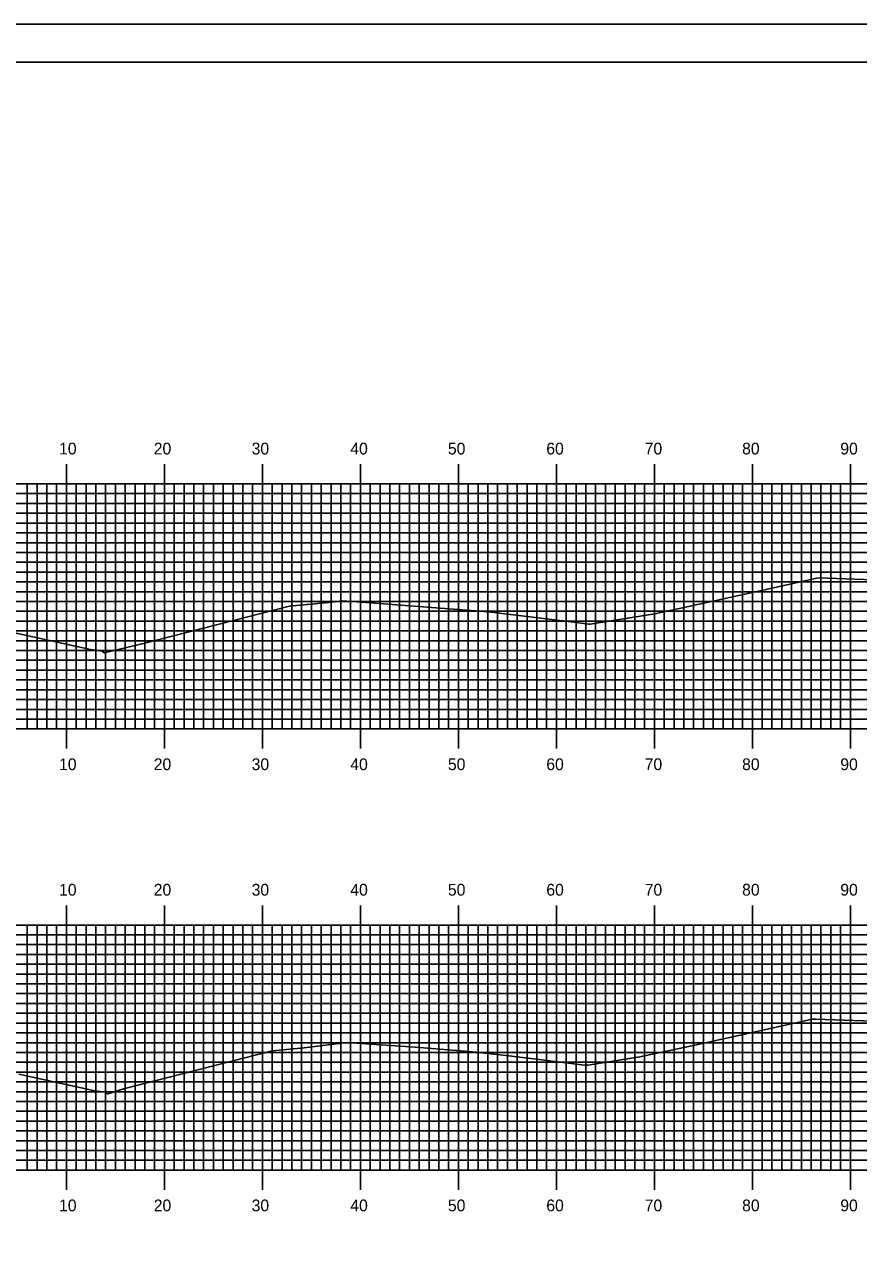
# Model space of a CAD drawing. Extents: x 855468 to 855811, y 366605 to 366825.
# Drawn here: x 855639.3 to 855724.4, y 366701.1 to 366824.9 of the extents above; entities that cross this region are included whole.
import ezdxf

# ---------------------------------------------------------------- set-up
doc = ezdxf.new("R2010")
doc.units = 0
for name, color, linetype in [('BORDER', 7, 'Continuous'), ('H_V ANNOTATION', 7, 'Continuous'), ('MAJOR', 7, 'Continuous'), ('MINOR', 7, 'Continuous'), ('PLOT BOUNDARY', 7, 'Continuous'), ('S_Roadway_Centerline', 7, 'Continuous')]:
    doc.layers.add(name, color=color, linetype=linetype)

msp = doc.modelspace()

# ---------------------------------------------------------------- linework, layer by layer
at = {"layer": 'BORDER'}
msp.add_lwpolyline([(855483.98, 366611.06), (855803.98, 366611.06), (855803.98, 366821.06), (855483.98, 366821.06)], close=True, dxfattribs=at)
at = {"layer": 'MAJOR'}
for p, q in [((855643.58, 366780.06), (855643.58, 366778.06)), ((855653.58, 366780.06), (855653.58, 366778.06)), ((855663.58, 366780.06), (855663.58, 366778.06)), ((855673.58, 366780.06), (855673.58, 366778.06)), ((855683.58, 366780.06), (855683.58, 366778.06)), ((855693.58, 366780.06), (855693.58, 366778.06)), ((855703.58, 366780.06), (855703.58, 366778.06)), ((855713.58, 366780.06), (855713.58, 366778.06)), ((855723.58, 366780.06), (855723.58, 366778.06)), ((855493.58, 366778.06), (855773.58, 366778.06)), ((855493.58, 366778.06), (855773.58, 366778.06)), ((855643.58, 366753.06), (855643.58, 366778.06)), ((855653.58, 366753.06), (855653.58, 366778.06)), ((855663.58, 366753.06), (855663.58, 366778.06)), ((855673.58, 366753.06), (855673.58, 366778.06)), ((855683.58, 366753.06), (855683.58, 366778.06)), ((855693.58, 366753.06), (855693.58, 366778.06)), ((855703.58, 366753.06), (855703.58, 366778.06)), ((855713.58, 366753.06), (855713.58, 366778.06)), ((855723.58, 366753.06), (855723.58, 366778.06)), ((855493.58, 366773.06), (855773.58, 366773.06)), ((855493.58, 366768.06), (855773.58, 366768.06)), ((855493.58, 366763.06), (855773.58, 366763.06)), ((855493.58, 366758.06), (855773.58, 366758.06)), ((855493.58, 366753.06), (855773.58, 366753.06)), ((855493.58, 366753.06), (855773.58, 366753.06)), ((855643.58, 366751.05), (855643.58, 366753.06)), ((855653.58, 366751.05), (855653.58, 366753.06)), ((855663.58, 366751.05), (855663.58, 366753.06)), ((855673.58, 366751.05), (855673.58, 366753.06)), ((855683.58, 366751.05), (855683.58, 366753.06)), ((855693.58, 366751.05), (855693.58, 366753.06)), ((855703.58, 366751.05), (855703.58, 366753.06)), ((855713.58, 366751.05), (855713.58, 366753.06)), ((855723.58, 366751.05), (855723.58, 366753.06)), ((855643.58, 366735.06), (855643.58, 366733.06)), ((855653.58, 366735.06), (855653.58, 366733.06)), ((855663.58, 366735.06), (855663.58, 366733.06)), ((855673.58, 366735.06), (855673.58, 366733.06)), ((855683.58, 366735.06), (855683.58, 366733.06)), ((855693.58, 366735.06), (855693.58, 366733.06)), ((855703.58, 366735.06), (855703.58, 366733.06)), ((855713.58, 366735.06), (855713.58, 366733.06)), ((855723.58, 366735.06), (855723.58, 366733.06)), ((855493.58, 366733.06), (855773.58, 366733.06)), ((855493.58, 366733.06), (855773.58, 366733.06)), ((855643.58, 366708.06), (855643.58, 366733.06)), ((855653.58, 366708.06), (855653.58, 366733.06)), ((855663.58, 366708.06), (855663.58, 366733.06)), ((855673.58, 366708.06), (855673.58, 366733.06)), ((855683.58, 366708.06), (855683.58, 366733.06)), ((855693.58, 366708.06), (855693.58, 366733.06)), ((855703.58, 366708.06), (855703.58, 366733.06)), ((855713.58, 366708.06), (855713.58, 366733.06)), ((855723.58, 366708.06), (855723.58, 366733.06)), ((855493.58, 366728.06), (855773.58, 366728.06)), ((855493.58, 366723.06), (855773.58, 366723.06)), ((855493.58, 366718.06), (855773.58, 366718.06)), ((855493.58, 366713.06), (855773.58, 366713.06)), ((855493.58, 366708.06), (855773.58, 366708.06)), ((855493.58, 366708.06), (855773.58, 366708.06)), ((855643.58, 366706.05), (855643.58, 366708.06)), ((855653.58, 366706.05), (855653.58, 366708.06)), ((855663.58, 366706.05), (855663.58, 366708.06)), ((855673.58, 366706.05), (855673.58, 366708.06)), ((855683.58, 366706.05), (855683.58, 366708.06)), ((855693.58, 366706.05), (855693.58, 366708.06)), ((855703.58, 366706.05), (855703.58, 366708.06)), ((855713.58, 366706.05), (855713.58, 366708.06)), ((855723.58, 366706.05), (855723.58, 366708.06))]:
    msp.add_line(p, q, dxfattribs=at)
at = {"layer": 'MINOR'}
for p, q in [((855639.58, 366753.06), (855639.58, 366778.06)), ((855640.58, 366753.06), (855640.58, 366778.06)), ((855641.58, 366753.06), (855641.58, 366778.06)), ((855642.58, 366753.06), (855642.58, 366778.06)), ((855644.58, 366753.06), (855644.58, 366778.06)), ((855645.58, 366753.06), (855645.58, 366778.06)), ((855646.58, 366753.06), (855646.58, 366778.06)), ((855647.58, 366753.06), (855647.58, 366778.06)), ((855648.58, 366753.06), (855648.58, 366778.06)), ((855649.58, 366753.06), (855649.58, 366778.06)), ((855650.58, 366753.06), (855650.58, 366778.06)), ((855651.58, 366753.06), (855651.58, 366778.06)), ((855652.58, 366753.06), (855652.58, 366778.06)), ((855654.58, 366753.06), (855654.58, 366778.06)), ((855655.58, 366753.06), (855655.58, 366778.06)), ((855656.58, 366753.06), (855656.58, 366778.06)), ((855657.58, 366753.06), (855657.58, 366778.06)), ((855658.58, 366753.06), (855658.58, 366778.06)), ((855659.58, 366753.06), (855659.58, 366778.06)), ((855660.58, 366753.06), (855660.58, 366778.06)), ((855661.58, 366753.06), (855661.58, 366778.06)), ((855662.58, 366753.06), (855662.58, 366778.06)), ((855664.58, 366753.06), (855664.58, 366778.06)), ((855665.58, 366753.06), (855665.58, 366778.06)), ((855666.58, 366753.06), (855666.58, 366778.06)), ((855667.58, 366753.06), (855667.58, 366778.06)), ((855668.58, 366753.06), (855668.58, 366778.06)), ((855669.58, 366753.06), (855669.58, 366778.06)), ((855670.58, 366753.06), (855670.58, 366778.06)), ((855671.58, 366753.06), (855671.58, 366778.06)), ((855672.58, 366753.06), (855672.58, 366778.06)), ((855674.58, 366753.06), (855674.58, 366778.06)), ((855675.58, 366753.06), (855675.58, 366778.06)), ((855676.58, 366753.06), (855676.58, 366778.06)), ((855677.58, 366753.06), (855677.58, 366778.06)), ((855678.58, 366753.06), (855678.58, 366778.06)), ((855679.58, 366753.06), (855679.58, 366778.06)), ((855680.58, 366753.06), (855680.58, 366778.06)), ((855681.58, 366753.06), (855681.58, 366778.06)), ((855682.58, 366753.06), (855682.58, 366778.06)), ((855684.58, 366753.06), (855684.58, 366778.06)), ((855685.58, 366753.06), (855685.58, 366778.06)), ((855686.58, 366753.06), (855686.58, 366778.06)), ((855687.58, 366753.06), (855687.58, 366778.06)), ((855688.58, 366753.06), (855688.58, 366778.06)), ((855689.58, 366753.06), (855689.58, 366778.06)), ((855690.58, 366753.06), (855690.58, 366778.06)), ((855691.58, 366753.06), (855691.58, 366778.06)), ((855692.58, 366753.06), (855692.58, 366778.06)), ((855694.58, 366753.06), (855694.58, 366778.06)), ((855695.58, 366753.06), (855695.58, 366778.06)), ((855696.58, 366753.06), (855696.58, 366778.06)), ((855697.58, 366753.06), (855697.58, 366778.06)), ((855698.58, 366753.06), (855698.58, 366778.06)), ((855699.58, 366753.06), (855699.58, 366778.06)), ((855700.58, 366753.06), (855700.58, 366778.06)), ((855701.58, 366753.06), (855701.58, 366778.06)), ((855702.58, 366753.06), (855702.58, 366778.06)), ((855704.58, 366753.06), (855704.58, 366778.06)), ((855705.58, 366753.06), (855705.58, 366778.06)), ((855706.58, 366753.06), (855706.58, 366778.06)), ((855707.58, 366753.06), (855707.58, 366778.06)), ((855708.58, 366753.06), (855708.58, 366778.06)), ((855709.58, 366753.06), (855709.58, 366778.06)), ((855710.58, 366753.06), (855710.58, 366778.06)), ((855711.58, 366753.06), (855711.58, 366778.06)), ((855712.58, 366753.06), (855712.58, 366778.06)), ((855714.58, 366753.06), (855714.58, 366778.06)), ((855715.58, 366753.06), (855715.58, 366778.06)), ((855716.58, 366753.06), (855716.58, 366778.06)), ((855717.58, 366753.06), (855717.58, 366778.06)), ((855718.58, 366753.06), (855718.58, 366778.06)), ((855719.58, 366753.06), (855719.58, 366778.06)), ((855720.58, 366753.06), (855720.58, 366778.06)), ((855721.58, 366753.06), (855721.58, 366778.06)), ((855722.58, 366753.06), (855722.58, 366778.06)), ((855493.58, 366777.06), (855773.58, 366777.06)), ((855493.58, 366776.06), (855773.58, 366776.06)), ((855493.58, 366775.06), (855773.58, 366775.06)), ((855493.58, 366774.06), (855773.58, 366774.06)), ((855493.58, 366772.06), (855773.58, 366772.06)), ((855493.58, 366771.06), (855773.58, 366771.06)), ((855493.58, 366770.06), (855773.58, 366770.06)), ((855493.58, 366769.06), (855773.58, 366769.06)), ((855493.58, 366767.06), (855773.58, 366767.06)), ((855493.58, 366766.06), (855773.58, 366766.06)), ((855493.58, 366765.06), (855773.58, 366765.06)), ((855493.58, 366764.06), (855773.58, 366764.06)), ((855493.58, 366762.06), (855773.58, 366762.06)), ((855493.58, 366761.06), (855773.58, 366761.06)), ((855493.58, 366760.06), (855773.58, 366760.06)), ((855493.58, 366759.06), (855773.58, 366759.06)), ((855493.58, 366757.06), (855773.58, 366757.06)), ((855493.58, 366756.06), (855773.58, 366756.06)), ((855493.58, 366755.06), (855773.58, 366755.06)), ((855493.58, 366754.06), (855773.58, 366754.06)), ((855639.58, 366708.06), (855639.58, 366733.06)), ((855640.58, 366708.06), (855640.58, 366733.06)), ((855641.58, 366708.06), (855641.58, 366733.06)), ((855642.58, 366708.06), (855642.58, 366733.06)), ((855644.58, 366708.06), (855644.58, 366733.06)), ((855645.58, 366708.06), (855645.58, 366733.06)), ((855646.58, 366708.06), (855646.58, 366733.06)), ((855647.58, 366708.06), (855647.58, 366733.06)), ((855648.58, 366708.06), (855648.58, 366733.06)), ((855649.58, 366708.06), (855649.58, 366733.06)), ((855650.58, 366708.06), (855650.58, 366733.06)), ((855651.58, 366708.06), (855651.58, 366733.06)), ((855652.58, 366708.06), (855652.58, 366733.06)), ((855654.58, 366708.06), (855654.58, 366733.06)), ((855655.58, 366708.06), (855655.58, 366733.06)), ((855656.58, 366708.06), (855656.58, 366733.06)), ((855657.58, 366708.06), (855657.58, 366733.06)), ((855658.58, 366708.06), (855658.58, 366733.06)), ((855659.58, 366708.06), (855659.58, 366733.06)), ((855660.58, 366708.06), (855660.58, 366733.06)), ((855661.58, 366708.06), (855661.58, 366733.06)), ((855662.58, 366708.06), (855662.58, 366733.06)), ((855664.58, 366708.06), (855664.58, 366733.06)), ((855665.58, 366708.06), (855665.58, 366733.06)), ((855666.58, 366708.06), (855666.58, 366733.06)), ((855667.58, 366708.06), (855667.58, 366733.06)), ((855668.58, 366708.06), (855668.58, 366733.06)), ((855669.58, 366708.06), (855669.58, 366733.06)), ((855670.58, 366708.06), (855670.58, 366733.06)), ((855671.58, 366708.06), (855671.58, 366733.06)), ((855672.58, 366708.06), (855672.58, 366733.06)), ((855674.58, 366708.06), (855674.58, 366733.06)), ((855675.58, 366708.06), (855675.58, 366733.06)), ((855676.58, 366708.06), (855676.58, 366733.06)), ((855677.58, 366708.06), (855677.58, 366733.06)), ((855678.58, 366708.06), (855678.58, 366733.06)), ((855679.58, 366708.06), (855679.58, 366733.06)), ((855680.58, 366708.06), (855680.58, 366733.06)), ((855681.58, 366708.06), (855681.58, 366733.06)), ((855682.58, 366708.06), (855682.58, 366733.06)), ((855684.58, 366708.06), (855684.58, 366733.06)), ((855685.58, 366708.06), (855685.58, 366733.06)), ((855686.58, 366708.06), (855686.58, 366733.06)), ((855687.58, 366708.06), (855687.58, 366733.06)), ((855688.58, 366708.06), (855688.58, 366733.06)), ((855689.58, 366708.06), (855689.58, 366733.06)), ((855690.58, 366708.06), (855690.58, 366733.06)), ((855691.58, 366708.06), (855691.58, 366733.06)), ((855692.58, 366708.06), (855692.58, 366733.06)), ((855694.58, 366708.06), (855694.58, 366733.06)), ((855695.58, 366708.06), (855695.58, 366733.06)), ((855696.58, 366708.06), (855696.58, 366733.06)), ((855697.58, 366708.06), (855697.58, 366733.06)), ((855698.58, 366708.06), (855698.58, 366733.06)), ((855699.58, 366708.06), (855699.58, 366733.06)), ((855700.58, 366708.06), (855700.58, 366733.06)), ((855701.58, 366708.06), (855701.58, 366733.06)), ((855702.58, 366708.06), (855702.58, 366733.06)), ((855704.58, 366708.06), (855704.58, 366733.06)), ((855705.58, 366708.06), (855705.58, 366733.06)), ((855706.58, 366708.06), (855706.58, 366733.06)), ((855707.58, 366708.06), (855707.58, 366733.06)), ((855708.58, 366708.06), (855708.58, 366733.06)), ((855709.58, 366708.06), (855709.58, 366733.06)), ((855710.58, 366708.06), (855710.58, 366733.06)), ((855711.58, 366708.06), (855711.58, 366733.06)), ((855712.58, 366708.06), (855712.58, 366733.06)), ((855714.58, 366708.06), (855714.58, 366733.06)), ((855715.58, 366708.06), (855715.58, 366733.06)), ((855716.58, 366708.06), (855716.58, 366733.06)), ((855717.58, 366708.06), (855717.58, 366733.06)), ((855718.58, 366708.06), (855718.58, 366733.06)), ((855719.58, 366708.06), (855719.58, 366733.06)), ((855720.58, 366708.06), (855720.58, 366733.06)), ((855721.58, 366708.06), (855721.58, 366733.06)), ((855722.58, 366708.06), (855722.58, 366733.06)), ((855493.58, 366732.06), (855773.58, 366732.06)), ((855493.58, 366731.06), (855773.58, 366731.06)), ((855493.58, 366730.06), (855773.58, 366730.06)), ((855493.58, 366729.06), (855773.58, 366729.06)), ((855493.58, 366727.06), (855773.58, 366727.06)), ((855493.58, 366726.06), (855773.58, 366726.06)), ((855493.58, 366725.06), (855773.58, 366725.06)), ((855493.58, 366724.06), (855773.58, 366724.06)), ((855493.58, 366722.06), (855773.58, 366722.06)), ((855493.58, 366721.06), (855773.58, 366721.06)), ((855493.58, 366720.06), (855773.58, 366720.06)), ((855493.58, 366719.06), (855773.58, 366719.06)), ((855493.58, 366717.06), (855773.58, 366717.06)), ((855493.58, 366716.06), (855773.58, 366716.06)), ((855493.58, 366715.06), (855773.58, 366715.06)), ((855493.58, 366714.06), (855773.58, 366714.06)), ((855493.58, 366712.06), (855773.58, 366712.06)), ((855493.58, 366711.06), (855773.58, 366711.06)), ((855493.58, 366710.06), (855773.58, 366710.06)), ((855493.58, 366709.06), (855773.58, 366709.06))]:
    msp.add_line(p, q, dxfattribs=at)
at = {"layer": 'PLOT BOUNDARY'}
msp.add_lwpolyline([(855467.8, 366604.94), (855807.8, 366604.94), (855807.8, 366824.94), (855467.8, 366824.94)], close=True, dxfattribs=at)
at = {"layer": 'S_Roadway_Centerline'}
for points in [[(855637.35, 366763.08), (855646.02, 366761.18), (855647.23, 366761), (855647.42, 366760.83), (855648.16, 366761), (855651.57, 366761.81), (855666.34, 366765.57), (855670.71, 366765.99), (855671.7, 366766.12), (855673.26, 366766.01), (855686.66, 366764.99), (855695.64, 366763.91), (855696.89, 366763.76), (855696.97, 366763.75), (855697.01, 366763.75), (855703.63, 366764.81), (855705.96, 366765.31), (855713.59, 366766.99), (855719.25, 366768.25), (855720.29, 366768.46), (855727.82, 366768.19)], [(855638.71, 366717.86), (855646.47, 366716.16), (855647.55, 366716), (855647.74, 366715.84), (855647.79, 366715.83), (855649.54, 366716.39), (855664.57, 366720.22), (855667.83, 366720.53), (855672.24, 366721.09), (855679.16, 366720.59), (855685.06, 366720.14), (855689.02, 366719.67), (855696.18, 366718.8), (855696.61, 366718.76), (855696.82, 366718.77), (855702.09, 366719.61), (855707.72, 366720.82), (855719.71, 366723.45), (855720.05, 366723.45), (855725.85, 366723.24)]]:
    msp.add_lwpolyline(points, dxfattribs=at)

# ---------------------------------------------------------------- texts
at = {"layer": 'H_V ANNOTATION'}
for s, p in [('10', (855642.83, 366781.06)), ('20', (855652.49, 366781.06)), ('30', (855662.48, 366781.06)), ('40', (855672.55, 366781.06)), ('50', (855682.51, 366781.06)), ('60', (855692.55, 366781.06)), ('70', (855702.59, 366781.06)), ('80', (855712.53, 366781.06)), ('90', (855722.55, 366781.06)), ('10', (855642.83, 366748.86)), ('20', (855652.49, 366748.86)), ('30', (855662.48, 366748.86)), ('40', (855672.55, 366748.86)), ('50', (855682.51, 366748.86)), ('60', (855692.55, 366748.86)), ('70', (855702.59, 366748.86)), ('80', (855712.53, 366748.86)), ('90', (855722.55, 366748.86)), ('10', (855642.83, 366736.06)), ('20', (855652.49, 366736.06)), ('30', (855662.48, 366736.06)), ('40', (855672.55, 366736.06)), ('50', (855682.51, 366736.06)), ('60', (855692.55, 366736.06)), ('70', (855702.59, 366736.06)), ('80', (855712.53, 366736.06)), ('90', (855722.55, 366736.06)), ('10', (855642.83, 366703.86)), ('20', (855652.49, 366703.86)), ('30', (855662.48, 366703.86)), ('40', (855672.55, 366703.86)), ('50', (855682.51, 366703.86)), ('60', (855692.55, 366703.86)), ('70', (855702.59, 366703.86)), ('80', (855712.53, 366703.86)), ('90', (855722.55, 366703.86))]:
    msp.add_text(s, height=1.2, dxfattribs=at).set_placement(p)

doc.saveas('drawing.dxf')
